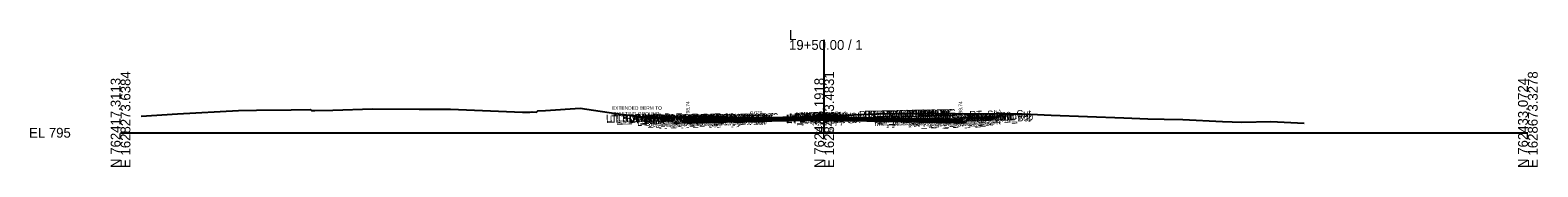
# Model space of a CAD drawing. Extents: x -26 to 4403, y -510 to 9556.
# Drawn here: x -25.7 to 402.8, y 9490.3 to 9529.2 of the extents above; entities that cross this region are included whole.
import ezdxf

# ---------------------------------------------------------------- set-up
doc = ezdxf.new("R2010")
doc.units = 0
for name, color, linetype in [('Default', 7, 'Continuous'), ('Exist Cross Section Cell', 7, 'Continuous'), ('Exist XS Center Line Elevation Label', 7, 'Continuous'), ('Exist XS Ground Line', 7, 'Continuous'), ('Prop CMT Conc Surface', 7, 'Continuous'), ('Prop CMT Concrete Structures', 7, 'Continuous'), ('Prop CMT Pvmt Course 1', 7, 'Continuous'), ('Prop CMT Pvmt Course 1 CG', 7, 'Continuous'), ('Prop CMT Pvmt Course 2', 7, 'Continuous'), ('Prop CMT Pvmt Course 3', 7, 'Continuous'), ('Prop CMT Pvmt Surface', 7, 'Continuous'), ('Prop CMT Pvmt Wedge Surface 1', 7, 'Continuous'), ('Prop CMT Pvmt Wedge Surface 2', 7, 'Continuous'), ('Prop CMT Pvmt Wedge Surface 3', 7, 'Continuous'), ('Prop CMT Slope Grass', 7, 'Continuous'), ('Prop CMT Subgrade Earthwork', 7, 'Continuous'), ('Prop XS Hydro Elevations', 7, 'Continuous'), ('Prop XS SE Text', 7, 'Continuous'), ('Prop XS Side Slope Text', 7, 'Continuous'), ('Scratch_Level_0', 7, 'Continuous')]:
    doc.layers.add(name, color=color, linetype=linetype)

msp = doc.modelspace()

# ---------------------------------------------------------------- linework, layer by layer
at = {"layer": 'Exist Cross Section Cell'}
for p, q in [((200, 9500), (200, 9526.39)), ((0, 9500), (200, 9500)), ((200, 9500), (400, 9500))]:
    msp.add_line(p, q, dxfattribs=at)
at = {"layer": 'Exist XS Ground Line'}
msp.add_lwpolyline([(5.82, 9504.74), (16.21, 9505.43), (33.52, 9506.3), (38.66, 9506.43), (48.46, 9506.5), (53.98, 9506.62), (54.29, 9506.33), (55.25, 9506.34), (60.37, 9506.46), (71.64, 9506.79), (84.87, 9506.69), (93.74, 9506.72), (114.26, 9505.82), (116.33, 9505.82), (116.95, 9505.91), (118.21, 9505.82), (118.63, 9506.25), (120.82, 9506.3), (130.6, 9506.98), (142.63, 9505.2), (145.02, 9505.02), (147.26, 9504.48), (148.44, 9504.46), (149.17, 9504.47), (149.72, 9504.04), (160.85, 9504.51), (162.19, 9504.54), (171.33, 9504.6), (180.81, 9503.99), (181.22, 9503.97), (182.04, 9503.97), (190.89, 9504.14), (191.96, 9504.07), (192.67, 9504.02), (195.94, 9504.45), (198.46, 9504.7), (200, 9504.75), (202.08, 9504.81), (204.51, 9504.95), (212.51, 9505.25), (214.99, 9505.34), (221.14, 9505.5), (232, 9505.52), (251.73, 9505.4), (255.7, 9505.38), (258.68, 9505.3), (264.48, 9505.05), (285.21, 9504.26), (291.95, 9503.99), (296.61, 9503.84), (301.94, 9503.75), (313.17, 9503.16), (318.73, 9503.02), (326.92, 9503.16), (336.42, 9502.72)], dxfattribs=at)
at = {"layer": 'Prop CMT Conc Surface'}
for points in [[(156.75, 9504.33), (151.75, 9504.43)], [(161.25, 9503.74), (161.25, 9504.24), (160.75, 9504.24)], [(163.25, 9503.86), (161.25, 9503.74)], [(236.75, 9503.86), (238.75, 9503.74)], [(238.75, 9503.74), (238.75, 9504.24), (239.25, 9504.24)], [(243.25, 9504.33), (248.25, 9504.43)]]:
    msp.add_lwpolyline(points, dxfattribs=at)
at = {"layer": 'Prop CMT Concrete Structures'}
for points in [[(202.24, 9504.55), (202.23, 9504.72), (201.48, 9504.97), (200.24, 9505), (199, 9504.98), (198.25, 9504.72), (198.24, 9504.56)], [(151.75, 9504.09), (151.75, 9504.43)], [(151.75, 9504.43), (156.75, 9504.33)], [(156.75, 9503.99), (151.75, 9504.09)], [(156.75, 9504.33), (156.75, 9503.99)], [(163.25, 9503.86), (161.25, 9503.74), (161.25, 9504.24), (160.75, 9504.24)], [(160.75, 9504.24), (160.75, 9503.23), (163.25, 9503.27)], [(163.25, 9503.27), (163.25, 9503.86)], [(198.24, 9504.56), (202.24, 9504.55)], [(236.75, 9503.86), (238.75, 9503.74), (238.75, 9504.24), (239.25, 9504.24)], [(239.25, 9504.24), (239.25, 9503.23), (236.75, 9503.27)], [(236.75, 9503.27), (236.75, 9503.86)], [(248.25, 9504.43), (243.25, 9504.33)], [(243.25, 9504.33), (243.25, 9503.99)], [(243.25, 9503.99), (248.25, 9504.09)], [(248.25, 9504.09), (248.25, 9504.43)]]:
    msp.add_lwpolyline(points, dxfattribs=at)
at = {"layer": 'Prop CMT Pvmt Course 1'}
for points in [[(198.24, 9504.56), (163.25, 9503.86)], [(163.25, 9503.61), (198.24, 9504.31)], [(163.25, 9503.86), (163.25, 9503.61)], [(175, 9503.84), (198.24, 9504.31)], [(198.24, 9504.56), (202.24, 9504.55)], [(198.24, 9504.31), (198.24, 9504.56)], [(198.24, 9504.31), (198.24, 9504.56)], [(202.24, 9504.3), (198.24, 9504.31)], [(202.24, 9504.55), (202.24, 9504.3)], [(202.24, 9504.55), (236.75, 9503.86)], [(202.24, 9504.3), (202.24, 9504.55)], [(236.75, 9503.61), (202.24, 9504.3)], [(225, 9503.84), (202.24, 9504.3)], [(236.75, 9503.86), (236.75, 9503.61)]]:
    msp.add_lwpolyline(points, dxfattribs=at)
at = {"layer": 'Prop CMT Pvmt Course 1 CG'}
for points in [[(163.25, 9503.27), (160.25, 9503.21), (159.91, 9502.88)], [(159.91, 9502.88), (163.25, 9502.94)], [(163.25, 9502.94), (163.25, 9503.27)], [(236.75, 9503.27), (239.75, 9503.21), (240.09, 9502.88)], [(236.75, 9502.94), (236.75, 9503.27)], [(240.09, 9502.88), (236.75, 9502.94)]]:
    msp.add_lwpolyline(points, dxfattribs=at)
at = {"layer": 'Prop CMT Pvmt Course 2'}
for points in [[(198.24, 9504.31), (163.25, 9503.61)], [(163.25, 9503.27), (198.24, 9503.97)], [(163.25, 9503.61), (163.25, 9503.27)], [(198.24, 9504.31), (175, 9503.84)], [(175, 9503.51), (198.24, 9503.98)], [(198.24, 9504.31), (202.24, 9504.3)], [(198.24, 9503.98), (198.24, 9504.31)], [(198.24, 9503.98), (198.24, 9504.31)], [(202.24, 9503.97), (198.24, 9503.98)], [(202.24, 9504.3), (202.24, 9503.97)], [(202.24, 9503.97), (202.24, 9504.3)], [(202.24, 9504.3), (225, 9503.84)], [(202.24, 9504.3), (236.75, 9503.61)], [(225, 9503.51), (202.24, 9503.97)], [(236.75, 9503.27), (202.24, 9503.97)], [(236.75, 9503.61), (236.75, 9503.27)]]:
    msp.add_lwpolyline(points, dxfattribs=at)
at = {"layer": 'Prop CMT Pvmt Course 3'}
for points in [[(198.24, 9503.97), (163.25, 9503.27)], [(163.25, 9502.94), (198.24, 9503.64)], [(163.25, 9503.27), (163.25, 9502.94)], [(198.24, 9503.98), (175, 9503.51)], [(175, 9503.18), (198.24, 9503.64)], [(198.24, 9503.98), (202.24, 9503.97)], [(198.24, 9503.64), (198.24, 9503.98)], [(198.24, 9503.64), (198.24, 9503.98)], [(202.24, 9503.63), (198.24, 9503.64)], [(202.24, 9503.97), (202.24, 9503.63)], [(202.24, 9503.97), (225, 9503.51)], [(202.24, 9503.63), (202.24, 9503.97)], [(202.24, 9503.97), (236.75, 9503.27)], [(225, 9503.18), (202.24, 9503.63)], [(236.75, 9502.94), (202.24, 9503.63)], [(236.75, 9503.27), (236.75, 9502.94)]]:
    msp.add_lwpolyline(points, dxfattribs=at)
at = {"layer": 'Prop CMT Pvmt Surface'}
for points in [[(198.24, 9504.56), (163.25, 9503.86)], [(198.24, 9504.56), (202.24, 9504.55)], [(202.24, 9504.55), (236.75, 9503.86)]]:
    msp.add_lwpolyline(points, dxfattribs=at)
at = {"layer": 'Prop CMT Pvmt Wedge Surface 1'}
for points in [[(198.24, 9504.31), (163.25, 9503.61)], [(163.25, 9503.61), (163.25, 9503.86)], [(198.24, 9504.31), (175, 9503.84)], [(198.24, 9504.56), (198.24, 9504.31)], [(202.24, 9504.55), (202.24, 9504.3)], [(202.24, 9504.3), (225, 9503.84)], [(202.24, 9504.3), (236.75, 9503.61)], [(236.75, 9503.61), (236.75, 9503.86)]]:
    msp.add_lwpolyline(points, dxfattribs=at)
at = {"layer": 'Prop CMT Pvmt Wedge Surface 2'}
for points in [[(163.25, 9503.61), (163.25, 9503.86)], [(198.24, 9504.56), (198.24, 9504.31)], [(202.24, 9504.55), (202.24, 9504.3)], [(236.75, 9503.61), (236.75, 9503.86)]]:
    msp.add_lwpolyline(points, dxfattribs=at)
at = {"layer": 'Prop CMT Pvmt Wedge Surface 3'}
for points in [[(163.25, 9503.27), (163.25, 9503.86)], [(198.24, 9504.56), (198.24, 9503.98)], [(202.24, 9504.55), (202.24, 9503.97)], [(236.75, 9503.27), (236.75, 9503.86)]]:
    msp.add_lwpolyline(points, dxfattribs=at)
at = {"layer": 'Prop CMT Slope Grass'}
for points in [[(248.25, 9504.42), (248.75, 9504.43), (251.67, 9505.4)], [(151.25, 9504.43), (147.15, 9504.51)], [(160.75, 9504.24), (151.25, 9504.43)], [(239.25, 9504.24), (248.25, 9504.42)]]:
    msp.add_lwpolyline(points, dxfattribs=at)
at = {"layer": 'Prop CMT Subgrade Earthwork'}
for points in [[(163.25, 9502.94), (159.91, 9502.88), (158.5, 9504.28)], [(198.24, 9503.64), (163.25, 9502.94)], [(198.24, 9503.64), (202.24, 9503.63)], [(202.24, 9503.63), (236.75, 9502.94)], [(236.75, 9502.94), (240.09, 9502.88), (241.5, 9504.28)]]:
    msp.add_lwpolyline(points, dxfattribs=at)

# ---------------------------------------------------------------- texts
at = {"layer": 'Default'}
msp.add_text('-', height=0.0001, dxfattribs=at).set_placement((0, 9500))
at = {"layer": 'Exist Cross Section Cell'}
for s, p in [('19+50.00 / 1', (190, 9523.59)), ('L', (190, 9526.39)), ('EL 795', (-26, 9498.6))]:
    msp.add_text(s, height=2.8, dxfattribs=at).set_placement(p)
for s, p in [('N 762417.3113', (0, 9490)), ('E 1628273.6384', (2.8, 9490)), ('N 762425.1918', (200, 9490)), ('E 1628473.4831', (202.8, 9490)), ('N 762433.0724', (400, 9490)), ('E 1628673.3278', (402.8, 9490))]:
    msp.add_text(s, height=2.8, rotation=90, dxfattribs=at).set_placement(p)
at = {"layer": 'Exist XS Center Line Elevation Label'}
msp.add_text('799.75', height=1.2, dxfattribs=at).set_placement((197.53, 9500.15))
at = {"layer": 'Prop XS Hydro Elevations'}
for p in [(161.75, 9504.74), (239.25, 9504.74)]:
    msp.add_text('798.74', height=1, rotation=90, dxfattribs=at).set_placement(p)
at = {"layer": 'Prop XS SE Text'}
for rotation, p in [(1.1445, (178.98, 9505.17)), (358.8546, (217.77, 9505.24))]:
    msp.add_text('0.020', height=1, rotation=rotation, dxfattribs=at).set_placement(p)
at = {"layer": 'Prop XS Side Slope Text'}
for s, p in [('EXTENDED BERM TO', (139.68, 9506.53)), ('EXISTING GROUND', (140.19, 9504.91))]:
    msp.add_text(s, height=1, dxfattribs=at).set_placement(p)
msp.add_text('3:1', height=1, rotation=18.4332, dxfattribs=at).set_placement((248.72, 9505.17))
at = {"layer": 'Scratch_Level_0'}
for s, p in [('LT_SDWK_Out_Top', (138.01, 9503.15)), ('LT_SDWK_Out_Bot', (138.04, 9502.82)), ('LT_Sub_Trench_Out_DLT', (139.09, 9502.9)), ('LT_Slope_Fill', (140.7, 9502.87)), ('LT_CSLP_Pnt', (141.45, 9503.23)), ('LT_SDWK_In_Top', (144.63, 9503.09)), ('LT_SDWK_In_Bot', (144.66, 9502.75)), ('LT_CG_Top_Face', (148.53, 9502.98)), ('LT_CG_Top_BOC', (149.06, 9503)), ('LT_CG_Top_Gut', (149.51, 9502.5)), ('19+50.00', (153.59, 9503.14)), ('LT_PV1_OEOT', (154.01, 9502.67)), ('19+50.00', (154.97, 9503.12)), ('LT_PV_Sub_Tie_Out', (159.98, 9503.06)), ('LT_PV_EG_TestPt', (161.43, 9503.09)), ('LT_PV_Sub_Tie_In', (161.57, 9503.1)), ('LT_PV_OEEOP_EG', (162.57, 9503.12)), ('LT_PV_IEEOP_EG', (163.21, 9503.13)), ('19+50.00', (163.31, 9503.31)), ('LT_PV2_OEEOP', (164.33, 9502.63)), ('LT_PV1_OEEOP', (164.9, 9502.77)), ('LT_PV2_IEEOP', (164.97, 9502.64)), ('LT_PV1_IEEOP', (165.54, 9502.78)), ('19+50.00', (168.82, 9503.24)), ('19+50.00', (168.84, 9503.24)), ('LT_PV2_PGL1', (189.14, 9503.13)), ('LT_PV3_PGL1', (189.14, 9502.79)), ('LT_PV2_PGL', (189.47, 9503.13)), ('LT_PV3_PGL', (189.47, 9502.8)), ('LT_PV1_PGL', (190.04, 9503.39)), ('MI_Face In', (190.16, 9503.56)), ('MI_Top In', (191.87, 9503.83)), ('19+50.00', (192.08, 9503.56)), ('19+50.00', (192.27, 9503.66)), ('MI_Face Out', (192.52, 9503.52)), ('MI_Top Out', (192.73, 9503.79)), ('RT_PV2_PGL1', (193.1, 9503.12)), ('RT_PV3_PGL1', (193.1, 9502.78)), ('MI_Crown', (193.33, 9503.86)), ('RT_PV2_PGL', (193.43, 9503.12)), ('RT_PV3_PGL', (193.43, 9502.79)), ('MI_Bot Out', (193.52, 9503.37)), ('RT_PV1_PGL', (193.99, 9503.38)), ('19+50.00', (195.55, 9503.76)), ('19+50.00', (196.07, 9503.46)), ('RT_PV_Sub_Tie_Out', (209.91, 9504.21)), ('RT_PV_EG_TestPt', (211.39, 9504.24)), ('RT_PV_Sub_Tie_In', (211.56, 9504.24)), ('RT_PV_OEEOP_EG', (212.52, 9504.26)), ('RT_PV_IEEOP_EG', (213.16, 9504.27)), ('RT_PV2_OEEOP', (214.28, 9502.63)), ('RT_PV1_OEEOP', (214.85, 9502.77)), ('RT_PV2_IEEOP', (214.93, 9502.64)), ('RT_PV1_IEEOP', (215.49, 9502.78)), ('19+50.00', (218.83, 9504.38)), ('19+50.00', (218.83, 9504.38)), ('RT_Sub_Trench_Out_DLT', (222.04, 9502.89)), ('19+50.00', (223.7, 9504.39)), ('RT_CG_Top_Face', (225.99, 9502.98)), ('RT_CG_Top_Gut', (226.96, 9502.5)), ('RT_PV1_OEOT', (227.47, 9502.67)), ('RT_CG_Top_BOC', (227.51, 9503)), ('RT_SDWK_In_Top', (231.08, 9503.09)), ('RT_SDWK_In_Bot', (231.11, 9502.75)), ('19+50.00', (232.78, 9503.12)), ('RT_SDWK_Out_Top', (234.46, 9503.15)), ('RT_SDWK_Out_Bot', (234.49, 9502.82)), ('19+50.00', (235.16, 9503.16)), ('19+50.00', (239.99, 9503.26)), ('RT_Shld_O', (240.81, 9503.27)), ('RT_Slope_Cut', (241.28, 9504.19)), ('CSLP_Pnt', (241.64, 9503.29)), ('19+50.00', (242.11, 9503.31)), ('LT_CG1_Shelf_Out', (146.82, 9501.95)), ('LT_CG_Bot_BOC', (149.09, 9501.99)), ('LT_Sub_OEOP', (150.04, 9501.68)), ('LT_Sub_OEOT_CG', (150.64, 9501.69)), ('LT_CG_Bot_IE', (153.19, 9502.07)), ('LT_Sub_OEOT', (153.35, 9501.74)), ('LT_PV2_OEOT', (153.45, 9502.41)), ('LT_PV3_OEOT', (153.45, 9502.08)), ('LT_Sub_OEEOP', (164.23, 9501.96)), ('LT_PV3_OEEOP', (164.33, 9502.3)), ('LT_Sub_IEEOP', (164.88, 9501.97)), ('LT_PV3_IEEOP', (164.97, 9502.31)), ('LT_Sub_PGL', (189.38, 9502.46)), ('LT_PV4_PGL', (189.47, 9502.47)), ('RT_Sub_PGL', (193.33, 9502.45)), ('RT_PV4_PGL', (193.43, 9502.46)), ('RT_Sub_OEEOP', (214.19, 9501.96)), ('RT_PV3_OEEOP', (214.28, 9502.3)), ('RT_Sub_IEEOP', (214.83, 9501.97)), ('RT_PV3_IEEOP', (214.93, 9502.31)), ('RT_Sub_OEOT_CG', (224.1, 9501.69)), ('RT_CG1_Shelf_Out', (226.28, 9501.95)), ('RT_CG_Bot_IE', (226.64, 9502.07)), ('RT_Sub_OEOT', (226.8, 9501.74)), ('RT_PV2_OEOT', (226.9, 9502.41)), ('RT_PV3_OEOT', (226.9, 9502.08)), ('RT_CG_Bot_BOC', (227.54, 9501.99)), ('RT_Sub_OEOP', (230.18, 9501.68))]:
    msp.add_text(s, height=2, rotation=1.1458, dxfattribs=at).set_placement(p)

doc.saveas('drawing.dxf')
